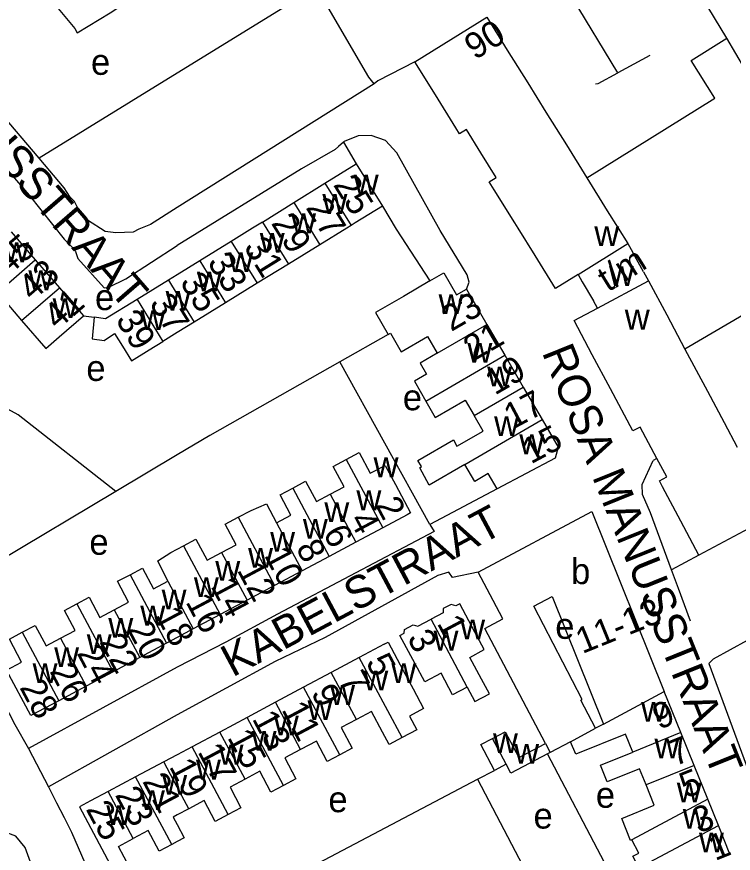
# Model space of a CAD drawing. Extents: x 159902 to 161769, y 383692 to 384875.
# Drawn here: x 160675.1 to 160786.3, y 383903 to 384032.8 of the extents above; entities that cross this region are included whole.
import ezdxf

# ---------------------------------------------------------------- set-up
doc = ezdxf.new("R2010")
doc.units = 0
for name, color, linetype in [('BLT_Basislijn', 7, 'Continuous'), ('BLT_Bebouwing', 7, 'Continuous'), ('BLT_Centroide', 7, 'Continuous'), ('BLT_Huisnummer', 7, 'Continuous'), ('BLT_Huisnummer_ tussenligend', 7, 'Continuous'), ('BLT_Huisnummer_reeks', 7, 'Continuous'), ('BLT_Onderdoorgang_en_onderverdeling', 7, 'Continuous'), ('BLT_Onderverdeling_panden', 7, 'Continuous'), ('BLT_Straatnaam', 7, 'Continuous')]:
    doc.layers.add(name, color=color, linetype=linetype)

msp = doc.modelspace()

# ---------------------------------------------------------------- linework, layer by layer
at = {"layer": 'BLT_Basislijn'}
for p, q in [((160721.6, 384037.33), (160700, 384024.04)), ((160768.37, 384024.07), (160761.01, 384036.24)), ((160773.34, 384026.76), (160768.37, 384024.07)), ((160678.56, 384010.84), (160667.52, 384023.83)), ((160700, 384024.04), (160678.56, 384010.84)), ((160730.55, 384022.37), (160700, 384003.16)), ((160725.78, 384013.32), (160727.79, 384009.98)), ((160732.74, 383983.5), (160725.22, 383979.24)), ((160725.22, 383979.24), (160705.07, 383967.82)), ((160739.22, 383953.99), (160725.22, 383979.24)), ((160705.07, 383967.82), (160700, 383964.8)), ((160700, 383964.8), (160690.47, 383959.11)), ((160690.47, 383959.11), (160664.32, 383943.52)), ((160749.64, 383959.53), (160739.22, 383953.99)), ((160780.96, 383949.26), (160776.71, 383946.99)), ((160700, 383931.89), (160676.93, 383919.27)), ((160700, 383924.5), (160680.01, 383913.3)), ((160676.93, 383919.27), (160680.01, 383913.3)), ((160746.59, 383914.49), (160749.24, 383915.88)), ((160700, 383890.04), (160746.59, 383914.49)), ((160746.59, 383914.49), (160756.14, 383896.34)), ((160680.01, 383913.3), (160681.26, 383910.86))]:
    msp.add_line(p, q, dxfattribs=at)
for points in [[(160679.44, 384036.6), (160684.09, 384030.92), (160684.47, 384030.26), (160689.62, 384033.35), (160695.93, 384037.62), (160697.53, 384038.52), (160700, 384040.14)], [(160730.55, 384022.37), (160729.74, 384023.39), (160721.6, 384037.33)], [(160763.56, 384007.78), (160783.4, 384020.15), (160779.77, 384025.98), (160785.28, 384029.42)], [(160659.77, 384024.99), (160661.45, 384023.04), (160677.02, 384005.07), (160682.46, 383998.27), (160683.74, 383997), (160684.22, 383996.36), (160684.59, 383995.28), (160688.68, 383990.74), (160689.41, 383990.83), (160692.03, 383992.12), (160700, 383997.28)], [(160736.89, 384025.75), (160731.13, 384022.84), (160730.55, 384022.37)], [(160764.88, 384022.37), (160765.33, 384022.42), (160768.37, 384024.07)], [(160744.9, 383990.5), (160745.29, 383991.58), (160744.99, 383992.76), (160740.82, 383999.63), (160734.1, 384011.66), (160732.34, 384013.57), (160730.11, 384014.37), (160728.1, 384014.29), (160725.89, 384013.42), (160725.78, 384013.32)], [(160725.78, 384013.32), (160725.04, 384012.64), (160724.53, 384012.17), (160719.26, 384009.17), (160700, 383997.28)], [(160694.05, 383999.81), (160693.17, 383999.36), (160690.5, 383999.24), (160688.84, 383999.47), (160686.07, 384001.24), (160684.85, 384002.56), (160684.06, 384004.1), (160683.37, 384004.78), (160682.46, 384006.24), (160678.56, 384010.84)], [(160700, 384003.16), (160695.85, 384000.55), (160694.05, 383999.81)], [(160731.84, 384003.4), (160733.97, 383999.82), (160739.21, 383991.8)], [(160808.64, 383988.77), (160803.06, 383986.17), (160799.11, 383993.1), (160778.79, 383981.22)], [(160690.47, 383959.11), (160675.33, 383971.02), (160671.5, 383973.08)], [(160776.71, 383946.99), (160773.44, 383955.81), (160772.18, 383958.66), (160772.13, 383960.21), (160773.86, 383963.95)], [(160739.22, 383953.99), (160739.85, 383952.92), (160715.55, 383940.11), (160707.55, 383935.76), (160700, 383931.89)], [(160779.64, 383939.03), (160777.79, 383944.09), (160776.71, 383946.99)], [(160746.68, 383946.63), (160742.73, 383945.8), (160742.13, 383946.64), (160740.44, 383946.12), (160722.94, 383936.51), (160715.2, 383932.78), (160700, 383924.5)], [(160664.32, 383943.52), (160665.13, 383941.64), (160674.8, 383922.98), (160676.93, 383919.27)], [(160789.94, 383933.21), (160788.45, 383936.02), (160783.16, 383933.13), (160782.49, 383932.48), (160794.23, 383900.62), (160795.68, 383898.07), (160797.42, 383896), (160797.84, 383895.65), (160800.29, 383894.78), (160802.93, 383894.69), (160805.42, 383895.54), (160806.44, 383896.13), (160818.93, 383905.69), (160830.31, 383913.34), (160841.85, 383920.77), (160849.53, 383926.4), (160850.93, 383927.2)], [(160766.3, 383901.61), (160757.48, 383918.42)], [(160681.26, 383910.86), (160682.46, 383908.59), (160683.59, 383906.28), (160684.65, 383903.93), (160685.64, 383901.56), (160686.55, 383899.15), (160687.38, 383896.72), (160688.14, 383894.26), (160688.83, 383891.78), (160689.43, 383889.28), (160689.68, 383888.16)], [(160689.27, 383870.48), (160684.45, 383880.61), (160683.78, 383882.49), (160683.26, 383884.97), (160676.41, 383903.93), (160674.94, 383905.66), (160673.06, 383906.41), (160670.67, 383906.49), (160664.62, 383903.62), (160648.63, 383894.85), (160606.51, 383872.87)]]:
    msp.add_lwpolyline(points, dxfattribs=at)
at = {"layer": 'BLT_Bebouwing'}
for p, q in [((160785.28, 384029.42), (160781.04, 384036.5)), ((160788.09, 384024.69), (160785.28, 384029.42)), ((160751.21, 384027.6), (160754.38, 384022.51)), ((160740.06, 384020.66), (160736.89, 384025.75)), ((160754.38, 384022.51), (160757.21, 384017.97)), ((160743.23, 384015.56), (160740.06, 384020.66)), ((160757.21, 384017.97), (160760.38, 384012.88)), ((160760.38, 384012.88), (160763.56, 384007.78)), ((160722.93, 384006.96), (160727.79, 384009.98)), ((160727.79, 384009.98), (160731.84, 384003.4)), ((160718.08, 384003.94), (160722.93, 384006.96)), ((160763.56, 384007.78), (160766.73, 384002.69)), ((160752.37, 384000.82), (160749.2, 384005.91)), ((160713.23, 384000.92), (160718.08, 384003.94)), ((160674.21, 383999.4), (160677.96, 383995.06)), ((160708.36, 383997.91), (160703.49, 383994.92)), ((160769.9, 383997.6), (160770.68, 383996.21)), ((160722.12, 383997.41), (160717.25, 383994.41)), ((160772.36, 383993.21), (160770.68, 383996.21)), ((160677.96, 383995.06), (160681.71, 383990.72)), ((160703.49, 383994.92), (160700, 383992.76)), ((160717.25, 383994.41), (160712.38, 383991.42)), ((160700, 383992.76), (160698.63, 383991.92)), ((160762.2, 383992.8), (160762.86, 383991.67)), ((160772.36, 383993.21), (160773.14, 383991.81)), ((160698.63, 383991.92), (160693.76, 383988.92)), ((160712.38, 383991.42), (160707.51, 383988.42)), ((160762.86, 383991.67), (160764.59, 383988.69)), ((160773.14, 383991.81), (160775.97, 383986.52)), ((160672.1, 383989.99), (160675.86, 383985.66)), ((160681.71, 383990.72), (160685.47, 383986.38)), ((160743.33, 383989.65), (160744.9, 383990.5)), ((160744.9, 383990.5), (160748.06, 383985.05)), ((160707.51, 383988.42), (160702.65, 383985.42)), ((160765.23, 383987.59), (160764.59, 383988.69)), ((160685.47, 383986.38), (160687.13, 383986.16)), ((160730.77, 383986.89), (160732.74, 383983.5)), ((160775.97, 383986.52), (160778.79, 383981.22)), ((160702.65, 383985.42), (160700, 383983.79)), ((160748.06, 383985.05), (160750.84, 383980.26)), ((160700, 383983.79), (160697.78, 383982.42)), ((160732.74, 383983.5), (160733.07, 383983.69)), ((160778.79, 383981.22), (160782.27, 383974.7)), ((160750.84, 383980.26), (160753.7, 383975.33)), ((160767.23, 383975.05), (160764.4, 383980.34)), ((160753.7, 383975.33), (160756.62, 383970.29)), ((160782.27, 383974.7), (160784.87, 383969.82)), ((160774.44, 383964.26), (160771.84, 383969.13)), ((160784.87, 383969.82), (160786.9, 383966.03)), ((160778.14, 383954.55), (160775.31, 383959.85)), ((160731.88, 383953.48), (160727.71, 383951.26)), ((160780.96, 383949.26), (160778.14, 383954.55)), ((160727.71, 383951.26), (160723.59, 383949.06)), ((160700, 383950.17), (160700.96, 383950.68)), ((160723.59, 383949.06), (160719.37, 383946.81)), ((160719.37, 383946.81), (160715.11, 383944.54)), ((160715.11, 383944.54), (160710.84, 383942.27)), ((160710.84, 383942.27), (160706.64, 383940.03)), ((160706.64, 383940.03), (160702.49, 383937.81)), ((160702.49, 383937.81), (160700, 383936.49)), ((160700, 383936.49), (160698.34, 383935.6)), ((160698.34, 383935.6), (160694.18, 383933.39)), ((160732.1, 383935.43), (160728.24, 383933.37)), ((160694.18, 383933.39), (160690.04, 383931.18)), ((160728.24, 383933.37), (160723.91, 383931.06)), ((160690.04, 383931.18), (160685.86, 383928.95)), ((160723.91, 383931.06), (160719.62, 383928.78)), ((160685.86, 383928.95), (160681.61, 383926.68)), ((160719.62, 383928.78), (160715.24, 383926.44)), ((160778.16, 383921.73), (160775.57, 383928.12)), ((160715.24, 383926.44), (160710.86, 383924.1)), ((160710.86, 383924.1), (160706.61, 383921.83)), ((160766.15, 383923.07), (160764.9, 383922.4)), ((160706.61, 383921.83), (160702.3, 383919.53)), ((160780.21, 383916.64), (160778.16, 383921.73)), ((160761.04, 383920.33), (160757.87, 383918.63)), ((160700, 383918.3), (160697.91, 383917.19)), ((160702.3, 383919.53), (160700, 383918.3)), ((160697.91, 383917.19), (160693.55, 383914.86)), ((160782.32, 383911.42), (160780.21, 383916.64)), ((160693.55, 383914.86), (160689.3, 383912.59)), ((160689.3, 383912.59), (160686.52, 383911.13)), ((160783.98, 383907.31), (160782.32, 383911.42)), ((160701.78, 383909.91), (160700, 383908.96)), ((160785.77, 383902.89), (160783.98, 383907.31)), ((160700, 383904.83), (160699.14, 383904.37))]:
    msp.add_line(p, q, dxfattribs=at)
for points in [[(160736.89, 384025.75), (160748.03, 384032.69), (160751.21, 384027.6)], [(160747.11, 384011.68), (160744.87, 384015.27), (160743.82, 384014.62), (160743.23, 384015.56)], [(160749.2, 384005.91), (160748.43, 384007.14), (160749.51, 384007.82), (160747.11, 384011.68)], [(160731.84, 384003.4), (160727.6, 384000.79), (160726.98, 384000.41)], [(160766.73, 384002.69), (160768.4, 384000), (160769.9, 383997.6)], [(160713.23, 384000.92), (160711.68, 383999.96), (160708.36, 383997.91)], [(160726.98, 384000.41), (160726.32, 384000), (160722.12, 383997.41)], [(160755.54, 383995.72), (160752.88, 384000), (160752.37, 384000.82)], [(160762.2, 383992.8), (160758.72, 383990.63), (160755.54, 383995.72)], [(160739.21, 383991.8), (160741.36, 383993.04), (160743.33, 383989.65)], [(160739.21, 383991.8), (160735.09, 383989.4), (160730.77, 383986.89)], [(160693.76, 383988.92), (160688.88, 383985.92), (160687.13, 383986.16)], [(160764.4, 383980.34), (160761.58, 383985.64), (160765.23, 383987.59)], [(160675.86, 383985.66), (160679.62, 383981.32), (160681.69, 383983.11), (160685.47, 383986.38)], [(160687.13, 383986.16), (160686.79, 383982.83), (160688.64, 383982.56), (160690.28, 383983.65), (160691.51, 383981.66), (160692.89, 383979.41), (160695.63, 383981.1), (160697.78, 383982.42)], [(160733.07, 383983.69), (160734.75, 383980.8), (160738.85, 383983.17), (160740.35, 383980.58)], [(160740.35, 383980.58), (160737.69, 383979.03), (160738.68, 383977.32), (160736.8, 383976.22), (160738.58, 383973.14)], [(160771.84, 383969.13), (160770.71, 383968.52), (160767.23, 383975.05)], [(160738.58, 383973.14), (160740.05, 383970.62), (160744.69, 383973.32), (160746.09, 383970.91)], [(160737.67, 383962.81), (160737.89, 383962.99), (160737.34, 383963.93), (160742.85, 383967.13), (160743.41, 383966.16), (160747.49, 383968.51), (160746.09, 383970.91)], [(160756.62, 383970.29), (160759.11, 383966), (160758.66, 383964.31), (160749.64, 383959.53)], [(160726.22, 383964.11), (160728.24, 383965.19), (160729.95, 383961.99), (160732.28, 383963.17), (160733.87, 383960.21), (160736.22, 383955.8), (160735.7, 383955.52), (160731.88, 383953.48)], [(160723.73, 383958.72), (160725.88, 383959.87), (160724.19, 383963.03), (160726.22, 383964.11)], [(160775.31, 383959.85), (160774.81, 383960.78), (160775.97, 383961.4), (160774.44, 383964.26)], [(160739.1, 383960.13), (160737.67, 383962.81)], [(160744.63, 383963.34), (160739.1, 383960.13)], [(160749.64, 383959.53), (160748.26, 383961.91), (160746.16, 383960.7), (160744.63, 383963.34)], [(160717.94, 383959.67), (160719.92, 383960.73), (160721.59, 383957.58), (160723.73, 383958.72)], [(160789.72, 383960.73), (160792.55, 383955.44), (160780.96, 383949.26)], [(160715.4, 383954.26), (160717.64, 383955.46), (160715.96, 383958.62), (160717.94, 383959.67)], [(160709.48, 383955.13), (160711.49, 383956.2), (160713.87, 383957.24), (160715.4, 383954.26)], [(160746.68, 383946.63), (160764.31, 383956.02), (160775.57, 383928.12)], [(160706.89, 383949.68), (160709.15, 383950.88), (160707.46, 383954.05), (160709.48, 383955.13)], [(160700.96, 383950.68), (160702.91, 383951.72), (160704.64, 383948.48), (160706.89, 383949.68)], [(160698.54, 383945.21), (160697, 383948.37), (160699.02, 383949.65), (160700, 383950.17)], [(160692.68, 383946.23), (160694.62, 383947.26), (160696.34, 383944.04), (160698.54, 383945.21)], [(160690.23, 383940.8), (160692.46, 383941.99), (160690.74, 383945.2), (160692.68, 383946.23)], [(160750.55, 383939.37), (160749.03, 383942.22), (160746.68, 383946.63)], [(160681.91, 383936.38), (160684.17, 383937.58), (160682.52, 383940.68), (160684.43, 383941.7)], [(160684.43, 383941.7), (160686.35, 383942.73), (160688.01, 383939.61), (160690.23, 383940.8)], [(160744.98, 383928.8), (160746.19, 383926.54), (160748.44, 383927.74), (160747.23, 383930), (160745.42, 383933.41), (160747.62, 383934.61), (160746.2, 383937.3), (160743.85, 383941.72), (160743.25, 383941.4), (160742.51, 383941.63), (160741.29, 383940.98), (160741.27, 383940.32), (160739.39, 383939.32)], [(160764.9, 383922.4), (160762.63, 383926.77), (160762.84, 383926.87), (160755.31, 383941.33), (160758.18, 383942.85), (160766.15, 383923.07)], [(160744.98, 383928.8), (160742.73, 383927.61), (160740.94, 383930.97), (160738.4, 383929.61), (160736.91, 383932.4), (160734.56, 383936.82), (160735.24, 383937.18), (160735.26, 383937.74), (160736.59, 383938.45), (160737.33, 383938.22), (160739.39, 383939.32)], [(160757.12, 383920.04), (160747.72, 383937.88), (160750.55, 383939.37)], [(160675.96, 383937.29), (160677.96, 383938.35), (160679.65, 383935.17), (160681.91, 383936.38)], [(160681.61, 383926.68), (160677.27, 383924.37), (160673.51, 383931.44), (160675.85, 383932.68), (160673.96, 383936.22), (160675.96, 383937.29)], [(160732.1, 383935.43), (160732.73, 383935.77), (160735.08, 383931.36), (160736.6, 383928.51), (160738.24, 383925.45), (160736.05, 383924.28), (160737.17, 383922.19), (160734.89, 383920.98)], [(160734.89, 383920.98), (160732.87, 383919.9), (160731.87, 383921.78), (160730.15, 383925.01), (160727.8, 383923.76)], [(160727.8, 383923.76), (160725.45, 383922.51), (160727.15, 383919.33), (160725.21, 383918.29)], [(160748.93, 383920.84), (160750.9, 383921.88), (160753.01, 383917.87), (160757.12, 383920.04)], [(160770.7, 383918.72), (160769.57, 383921.51), (160761.83, 383918.38), (160761.04, 383920.33)], [(160725.21, 383918.29), (160723.27, 383917.26), (160721.59, 383920.42), (160719.14, 383919.11)], [(160749.24, 383915.88), (160747.12, 383919.88), (160748.93, 383920.84)], [(160719.14, 383919.11), (160716.7, 383917.81), (160718.42, 383914.58), (160716.48, 383913.54)], [(160757.48, 383918.42), (160751.79, 383915.43), (160751.05, 383916.83)], [(160757.87, 383918.63), (160757.48, 383918.42)], [(160772.75, 383913.62), (160771.74, 383916.13), (160766.74, 383914.11), (160765.69, 383916.7), (160770.7, 383918.72)], [(160716.48, 383913.54), (160714.55, 383912.51), (160712.84, 383915.73), (160710.52, 383914.49)], [(160751.05, 383916.83), (160749.24, 383915.88)], [(160710.52, 383914.49), (160708.2, 383913.26), (160709.89, 383910.08), (160707.89, 383909.02)], [(160770.54, 383905.12), (160770.35, 383905.02), (160768.98, 383908.42), (160774.03, 383910.46), (160772.75, 383913.62)], [(160686.52, 383911.13), (160684.82, 383910.21), (160690.46, 383899.61), (160692.65, 383900.78), (160690.89, 383904.09), (160693.18, 383905.31)], [(160707.89, 383909.02), (160705.9, 383907.96), (160704.18, 383911.19), (160701.78, 383909.91)], [(160700, 383908.96), (160699.38, 383908.64), (160700, 383907.48)], [(160700, 383907.48), (160701.1, 383905.42), (160700, 383904.83)], [(160699.14, 383904.37), (160697.18, 383903.33), (160695.47, 383906.53), (160693.18, 383905.31)], [(160771.62, 383900.77), (160770.68, 383902.55), (160771.63, 383903.04), (160770.54, 383905.12)]]:
    msp.add_lwpolyline(points, dxfattribs=at)
at = {"layer": 'BLT_Onderdoorgang_en_onderverdeling'}
for p, q in [((160762.2, 383992.8), (160769.9, 383997.6)), ((160765.23, 383987.59), (160773.14, 383991.81))]:
    msp.add_line(p, q, dxfattribs=at)
at = {"layer": 'BLT_Onderverdeling_panden'}
for p, q in [((160722.93, 384006.96), (160726.98, 384000.41)), ((160718.08, 384003.94), (160722.12, 383997.41)), ((160713.23, 384000.92), (160717.25, 383994.41)), ((160708.36, 383997.91), (160712.38, 383991.42)), ((160672.1, 383989.99), (160677.96, 383995.06)), ((160703.49, 383994.92), (160707.51, 383988.42)), ((160698.63, 383991.92), (160700, 383989.7)), ((160675.86, 383985.66), (160681.71, 383990.72)), ((160700, 383989.7), (160702.65, 383985.42)), ((160693.76, 383988.92), (160697.78, 383982.42)), ((160740.35, 383980.58), (160748.06, 383985.05)), ((160738.58, 383973.14), (160750.84, 383980.26)), ((160746.09, 383970.91), (160753.7, 383975.33)), ((160744.63, 383963.34), (160756.62, 383970.29)), ((160726.22, 383964.11), (160731.88, 383953.48)), ((160774.44, 383964.26), (160773.86, 383963.95)), ((160717.94, 383959.67), (160723.59, 383949.06)), ((160723.73, 383958.72), (160727.71, 383951.26)), ((160709.48, 383955.13), (160715.11, 383944.54)), ((160715.4, 383954.26), (160719.37, 383946.81)), ((160700.96, 383950.68), (160706.64, 383940.03)), ((160706.89, 383949.68), (160710.84, 383942.27)), ((160692.68, 383946.23), (160698.34, 383935.6)), ((160698.54, 383945.21), (160700, 383942.48)), ((160684.43, 383941.7), (160690.04, 383931.18)), ((160700, 383942.48), (160702.49, 383937.81)), ((160690.23, 383940.8), (160694.18, 383933.39)), ((160744.98, 383928.8), (160739.39, 383939.32)), ((160675.96, 383937.29), (160681.61, 383926.68)), ((160681.91, 383936.38), (160685.86, 383928.95)), ((160734.89, 383920.98), (160728.24, 383933.37)), ((160727.8, 383923.76), (160723.91, 383931.06)), ((160725.21, 383918.29), (160719.62, 383928.78)), ((160766.15, 383923.07), (160775.57, 383928.12)), ((160719.14, 383919.11), (160715.24, 383926.44)), ((160716.48, 383913.54), (160710.86, 383924.1)), ((160761.04, 383920.33), (160764.9, 383922.4)), ((160710.52, 383914.49), (160706.61, 383921.83)), ((160778.16, 383921.73), (160770.7, 383918.72)), ((160751.05, 383916.83), (160748.93, 383920.84)), ((160757.12, 383920.04), (160757.87, 383918.63)), ((160707.89, 383909.02), (160702.3, 383919.53)), ((160700, 383913.26), (160697.91, 383917.19)), ((160780.21, 383916.64), (160772.75, 383913.62)), ((160699.14, 383904.37), (160693.55, 383914.86)), ((160701.78, 383909.91), (160700, 383913.26)), ((160693.18, 383905.31), (160689.3, 383912.59)), ((160782.32, 383911.42), (160770.54, 383905.12)), ((160771.62, 383900.77), (160783.98, 383907.31))]:
    msp.add_line(p, q, dxfattribs=at)

# ---------------------------------------------------------------- texts
at = {"layer": 'BLT_Centroide'}
for s, p in [('e', (160686.62, 384023.76)), ('w', (160727.39, 384005.19)), ('w', (160722.53, 384002.19)), ('w', (160717.67, 383999.19)), ('w', (160764.72, 383997.19)), ('w', (160712.81, 383996.17)), ('w', (160673.15, 383994.69)), ('w', (160707.94, 383993.17)), ('w', (160767.01, 383990.99)), ('w', (160676.91, 383990.34)), ('w', (160703.06, 383990.17)), ('e', (160687.24, 383987.27)), ('w', (160698.2, 383987.17)), ('w', (160740.56, 383986.64)), ('w', (160680.66, 383986.03)), ('w', (160694.31, 383984.16)), ('w', (160769.45, 383984.24)), ('w', (160745.03, 383979.09)), ('e', (160685.9, 383976.28)), ('w', (160748.09, 383975.44)), ('e', (160735.01, 383971.73)), ('w', (160749.17, 383967.72)), ('w', (160753.09, 383964.91)), ('w', (160730.47, 383961.34)), ('w', (160727.81, 383956.22)), ('w', (160722.83, 383954.38)), ('w', (160719.5, 383951.81)), ('e', (160686.37, 383949.32)), ('w', (160714.42, 383949.8)), ('w', (160711, 383947.3)), ('w', (160705.91, 383945.28)), ('b', (160761.12, 383944.78)), ('w', (160702.59, 383942.75)), ('w', (160697.58, 383940.86)), ('w', (160694.28, 383938.33)), ('w', (160689.31, 383936.44)), ('w', (160743.91, 383936.2)), ('e', (160758.66, 383936.28)), ('w', (160685.97, 383933.91)), ('w', (160739.77, 383934.47)), ('w', (160680.91, 383931.91)), ('w', (160677.56, 383929.41)), ('w', (160728.88, 383928.27)), ('w', (160733.23, 383929.41)), ('w', (160723.72, 383926.03)), ('w', (160720.22, 383923.67)), ('w', (160771.98, 383923.41)), ('w', (160715, 383921.31)), ('w', (160711.55, 383918.92)), ('w', (160749, 383918.57)), ('w', (160706.41, 383916.77)), ('w', (160752.29, 383916.92)), ('w', (160774.05, 383917.75)), ('w', (160702.91, 383914.45)), ('w', (160697.67, 383912.09)), ('e', (160764.96, 383910.08)), ('w', (160777.52, 383910.91)), ('w', (160694.22, 383909.73)), ('e', (160723.46, 383909.39)), ('w', (160689, 383907.39)), ('e', (160755.29, 383906.85)), ('w', (160778.44, 383906.84)), ('w', (160780.96, 383903.16))]:
    msp.add_text(s, height=4, dxfattribs=at).set_placement(p)
at = {"layer": 'BLT_Huisnummer'}
for s, rotation, p in [('25', 301.7354, (160724.13, 384006.71)), ('29', 301.7374, (160714.49, 384000.76)), ('45', 40.8887, (160673.79, 383992.48)), ('33', 301.7359, (160704.59, 383994.7)), ('41', 40.8959, (160681.42, 383984.09)), ('23', 30.126, (160742.51, 383983.86)), ('39', 301.6203, (160690.35, 383985.77)), ('19', 30.1115, (160749.28, 383973.99)), ('15', 28.0394, (160754.88, 383963.32)), ('2', 298.029, (160730.68, 383957.03)), ('6', 298.0268, (160722.55, 383952.68)), ('10', 298.0296, (160713.42, 383949.26)), ('14', 298.0248, (160705.11, 383944.48)), ('18', 298.0338, (160696.53, 383939.99)), ('1', 298.0326, (160740.24, 383938.71)), ('22', 298.0197, (160687.87, 383935.82)), ('5', 298.041, (160729.18, 383932.67)), ('28', 298.0342, (160675.47, 383928.76)), ('9', 298.0333, (160720.69, 383927.93)), ('9', 21.9932, (160774.77, 383922.15)), ('13', 298.0338, (160711.55, 383923.9)), ('17', 298.0335, (160703.1, 383918.79)), ('5', 21.9981, (160778.95, 383911.49)), ('21', 298.0473, (160694.53, 383914.19)), ('25', 298.045, (160685.75, 383909.88)), ('1', 21.9981, (160783.46, 383901.8))]:
    msp.add_text(s, height=4, rotation=rotation, dxfattribs=at).set_placement(p)
at = {"layer": 'BLT_Huisnummer_ tussenligend'}
for s, rotation, p in [('27', 301.7354, (160719.86, 384003.17)), ('31', 301.7374, (160710.23, 383997.05)), ('43', 40.8959, (160677.52, 383988.54)), ('35', 301.7359, (160700.33, 383991.61)), ('37', 301.7359, (160695.58, 383988.31)), ('21', 30.1115, (160745.91, 383979.24)), ('17', 28.0394, (160752.06, 383968.71)), ('4', 298.029, (160726.63, 383954.76)), ('8', 298.0268, (160718.34, 383950.39)), ('12', 298.0296, (160709.21, 383946.96)), ('16', 298.0248, (160701.24, 383942.02)), ('20', 298.0338, (160692.17, 383937.79)), ('3', 298.0326, (160735.61, 383936.41)), ('24', 298.0197, (160684.35, 383934.07)), ('26', 298.0197, (160680.14, 383931.26)), ('7', 298.041, (160725.14, 383929.99)), ('11', 298.0333, (160716.13, 383925.31)), ('15', 298.0338, (160707.71, 383921.01)), ('7', 21.9981, (160777.21, 383916.48)), ('19', 298.0335, (160698.68, 383916.48)), ('23', 298.0473, (160690.28, 383912.09)), ('3', 21.9981, (160780.93, 383906.05))]:
    msp.add_text(s, height=4, rotation=rotation, dxfattribs=at).set_placement(p)
at = {"layer": 'BLT_Huisnummer_reeks'}
for s, rotation, p in [('90', 31.9291, (160746.2, 384025.99)), ('t/m', 31.9231, (160766.85, 383989.99)), ('11-13', 21.9958, (160762.85, 383933.91))]:
    msp.add_text(s, height=4, rotation=rotation, dxfattribs=at).set_placement(p)
at = {"layer": 'BLT_Straatnaam'}
for s, rotation, p in [('ROSA MANUSSTRAAT', 310.901, (160645.31, 384040.98)), ('ROSA MANUSSTRAAT', 291.9943, (160756.54, 383980.73)), ('KABELSTRAAT', 28.0852, (160708.58, 383930.26))]:
    msp.add_text(s, height=5, rotation=rotation, dxfattribs=at).set_placement(p)

doc.saveas('drawing.dxf')
